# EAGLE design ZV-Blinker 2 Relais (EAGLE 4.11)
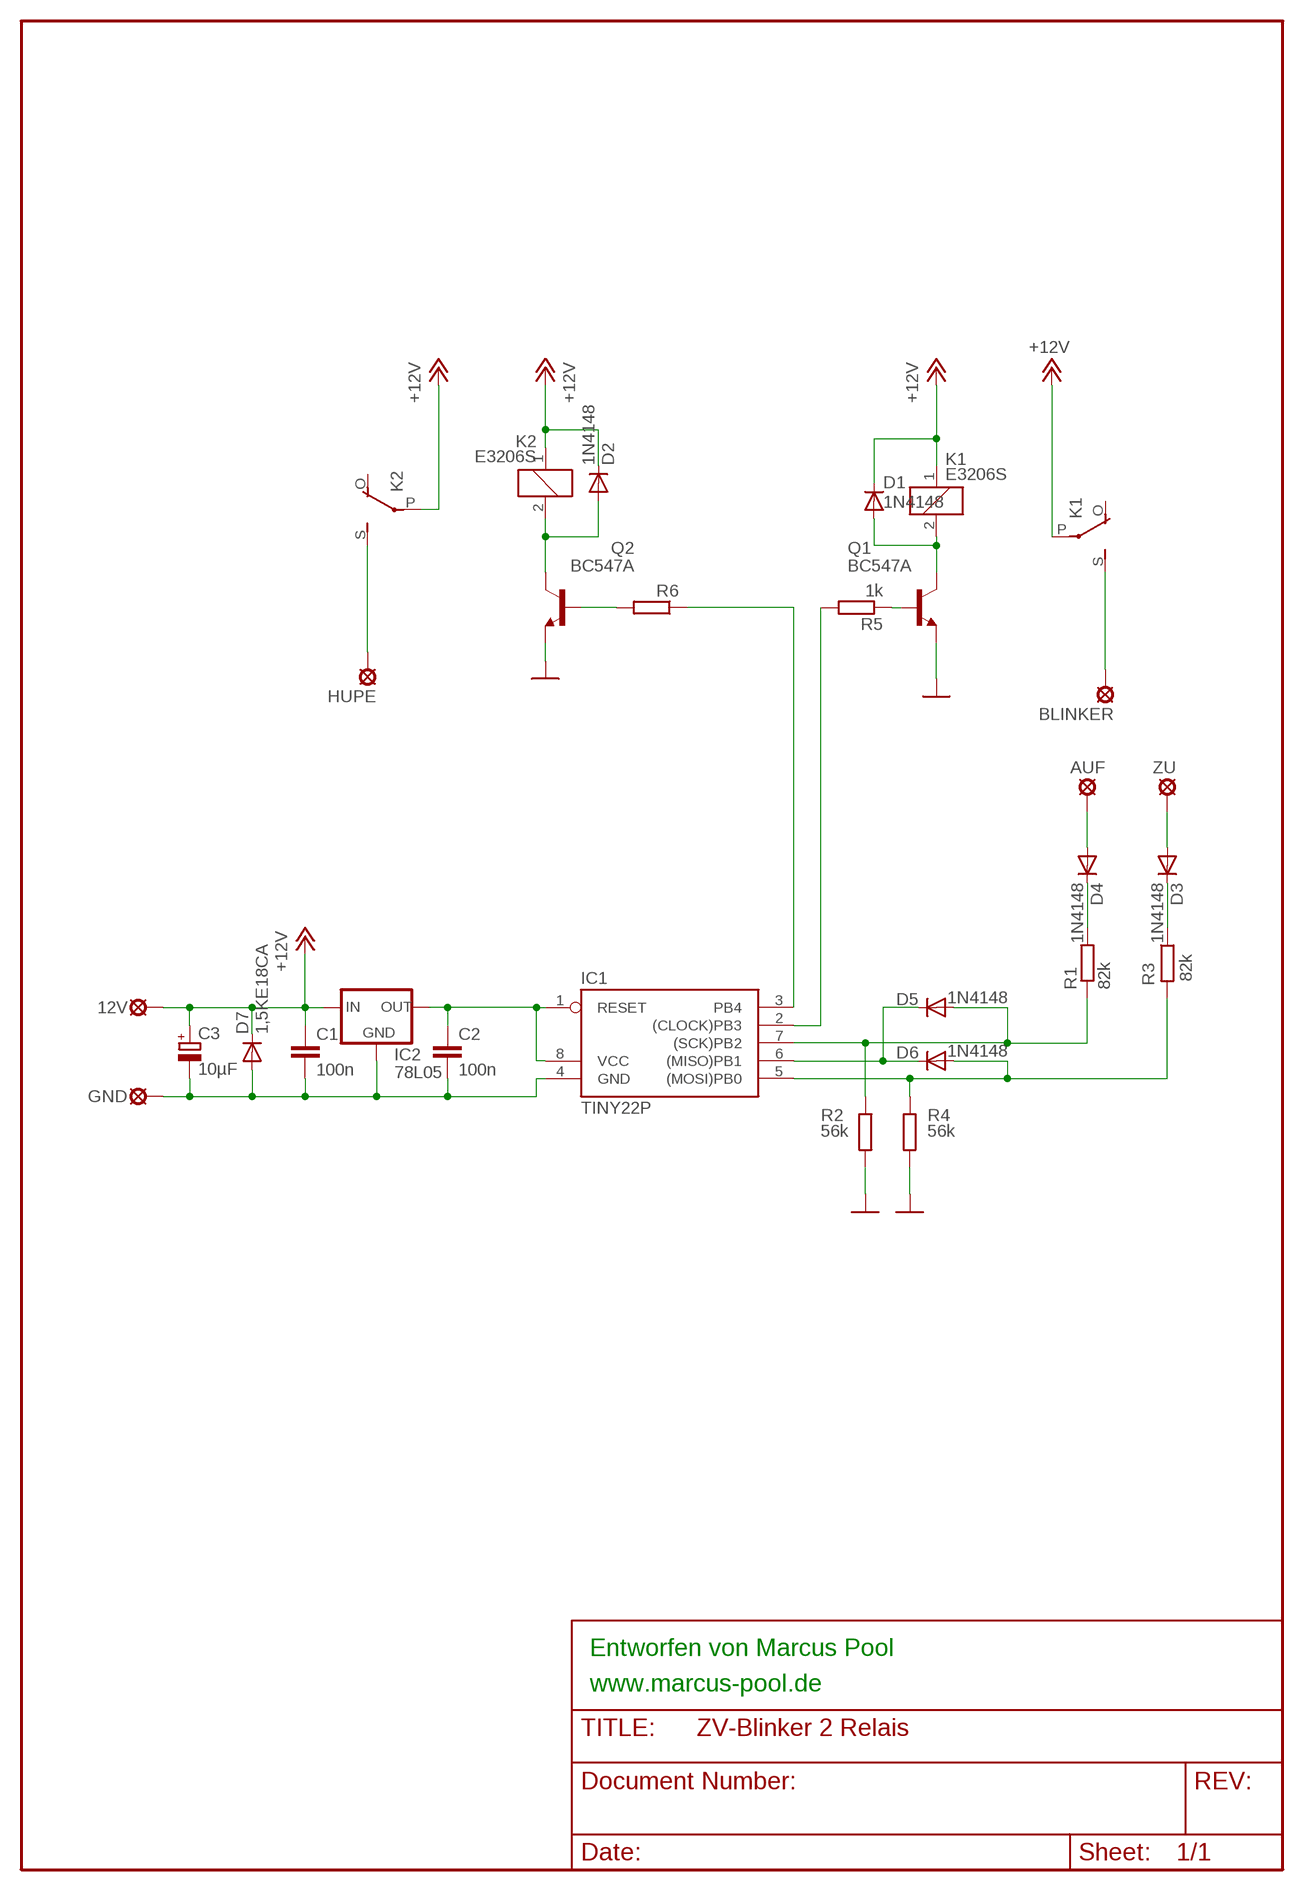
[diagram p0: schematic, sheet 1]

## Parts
12V  MCS08  [MCS08]
AUF  MCS08  [MCS08]
BLINKER  MCS08  [MCS08]
C1  100n  C-EU050-035X075  [C050-035X075]
C2  100n  C-EU050-035X075  [C050-035X075]
C3  10µF  CPOL-EUE2,5-6E  [E2,5-6E]
D1  1N4148  [DO35-10]
D2  1N4148  [DO35-10]
D3  1N4148  [DO35-10]
D4  1N4148  [DO35-10]
D5  1N4148  [DO35-10]
D6  1N4148  [DO35-10]
D7  1,5KE18CA  1N5060GP  [DO15-12]
GND  MCS08  [MCS08]
HUPE  MCS08  [MCS08]
IC1  TINY22P  [DIL08]
IC2  78L05  78LXX  [78LXX]
K1  E3206S  [E3206S]
K2  E3206S  [E3206S]
Q1  BC547A  [TO92]
Q2  BC547A  [TO92]
R1  82k  R-EU_0207/10  [0207/10]
R2  56k  R-EU_0207/10  [0207/10]
R3  82k  R-EU_0207/10  [0207/10]
R4  56k  R-EU_0207/10  [0207/10]
R5  1k  R-EU_0207/10  [0207/10]
R6  R-EU_0207/10  [0207/10]
ZU  MCS08  [MCS08]

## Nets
5V: C2.2 IC1.1(RESET) IC1.8(VCC) IC2.OUT
+12V: 12V.MP C1.2 C3.+ D1.C D2.C D7.C IC2.IN K1.1 K1.P(2:P) K2.1 K2.P(2:P)
GND: C1.1 C2.1 C3.- D7.A GND.MP IC1.4(GND) IC2.GND Q1.1(E) Q2.1(E) R2.2 R4.2 ; supply symbol labelled 
N$1: D5.A IC1.7((SCK)PB2) R1.1 R2.1
N$2: D5.C D6.C IC1.6((MISO)PB1)
N$3: BLINKER.MP K1.S(2:S)
N$4: D6.A IC1.5((MOSI)PB0) R3.2 R4.1
N$5: D3.A ZU.MP
N$6: Q1.2(B) R5.1
N$7: D1.A K1.2 Q1.3(C)
N$8: D3.C R3.1
N$9: AUF.MP D4.A
N$10: IC1.2((CLOCK)PB3) R5.2
N$11: D4.C R1.2
N$12: IC1.3(PB4) R6.1
N$13: Q2.2(B) R6.2
N$14: D2.A K2.2 Q2.3(C)
N$15: HUPE.MP K2.S(2:S)
Unconnected: K1.O(2:O) K2.O(2:O)

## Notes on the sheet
- Entworfen von Marcus Pool
- www.marcus-pool.de

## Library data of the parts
12V AUF BLINKER GND HUPE ZU = solpad:MCS08: SOLDER PAD
C1 C2 = rcl:C-EU: CAPACITOR, European symbol
C3 = rcl:CPOL-EU: POLARIZED CAPACITOR, European symbol
D1-D6 = diode:1N4148: DIODE
D7 = diode:1N5060GP: DIODE
IC1 = atmel:TINY22: MICROCONTROLLER 1K ROM 128 bytes RAM 128 bytes EEPROM
IC2 = v-reg:78LXX: VOLTAGE REGULATOR
K1 K2 = relay:E3206S: RELAY 1 x switch, Eichhoff/distributor Schukat
Q1 Q2 = transistor-npn:BC547*: NPN Transistor
R1-R6 = rcl:R-EU_: RESISTOR, European symbol

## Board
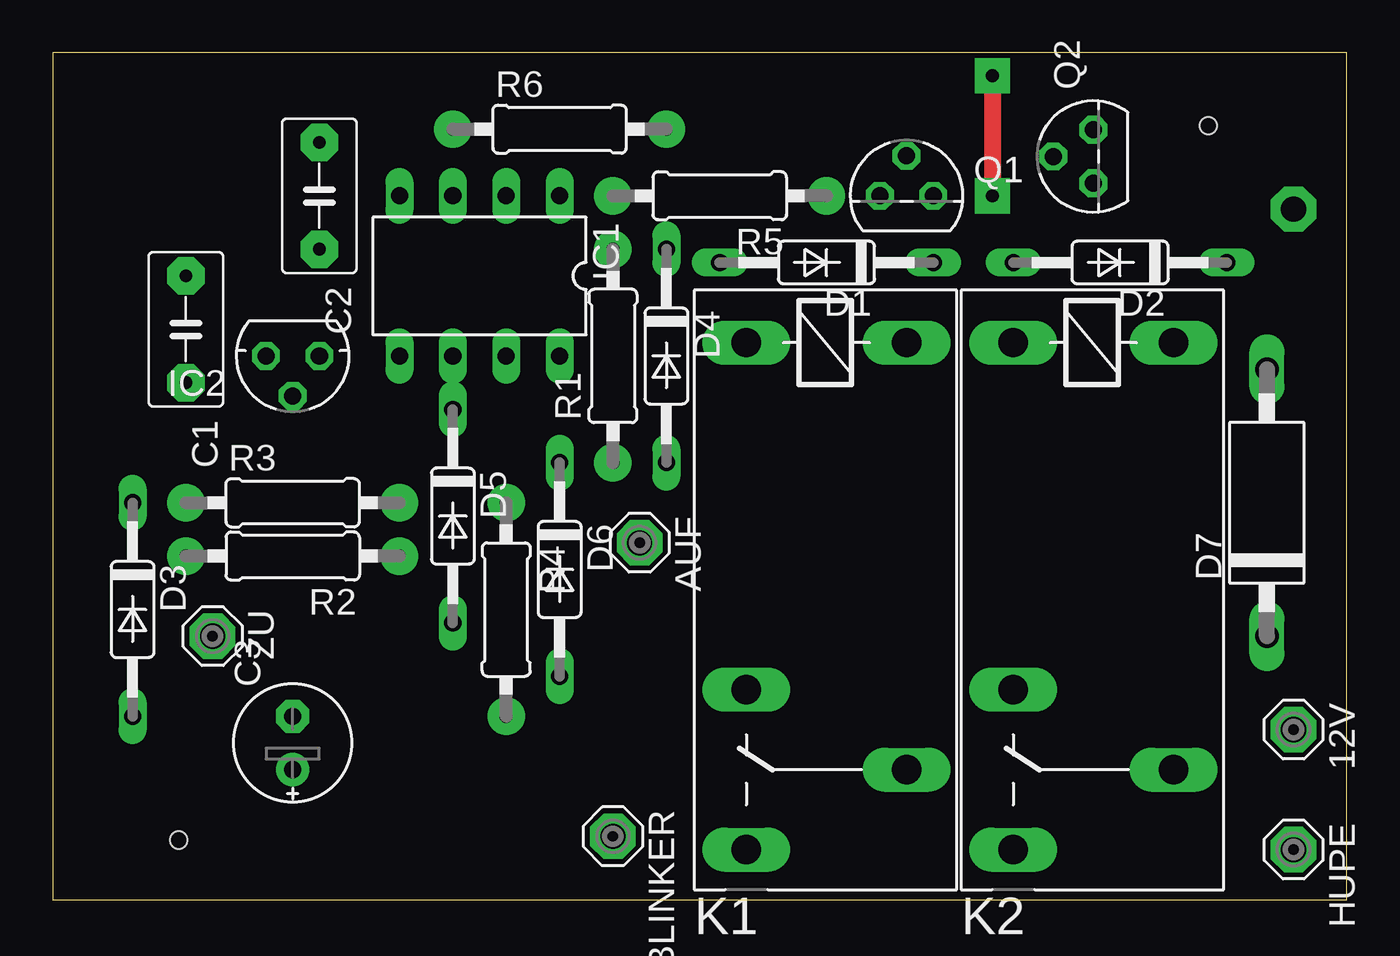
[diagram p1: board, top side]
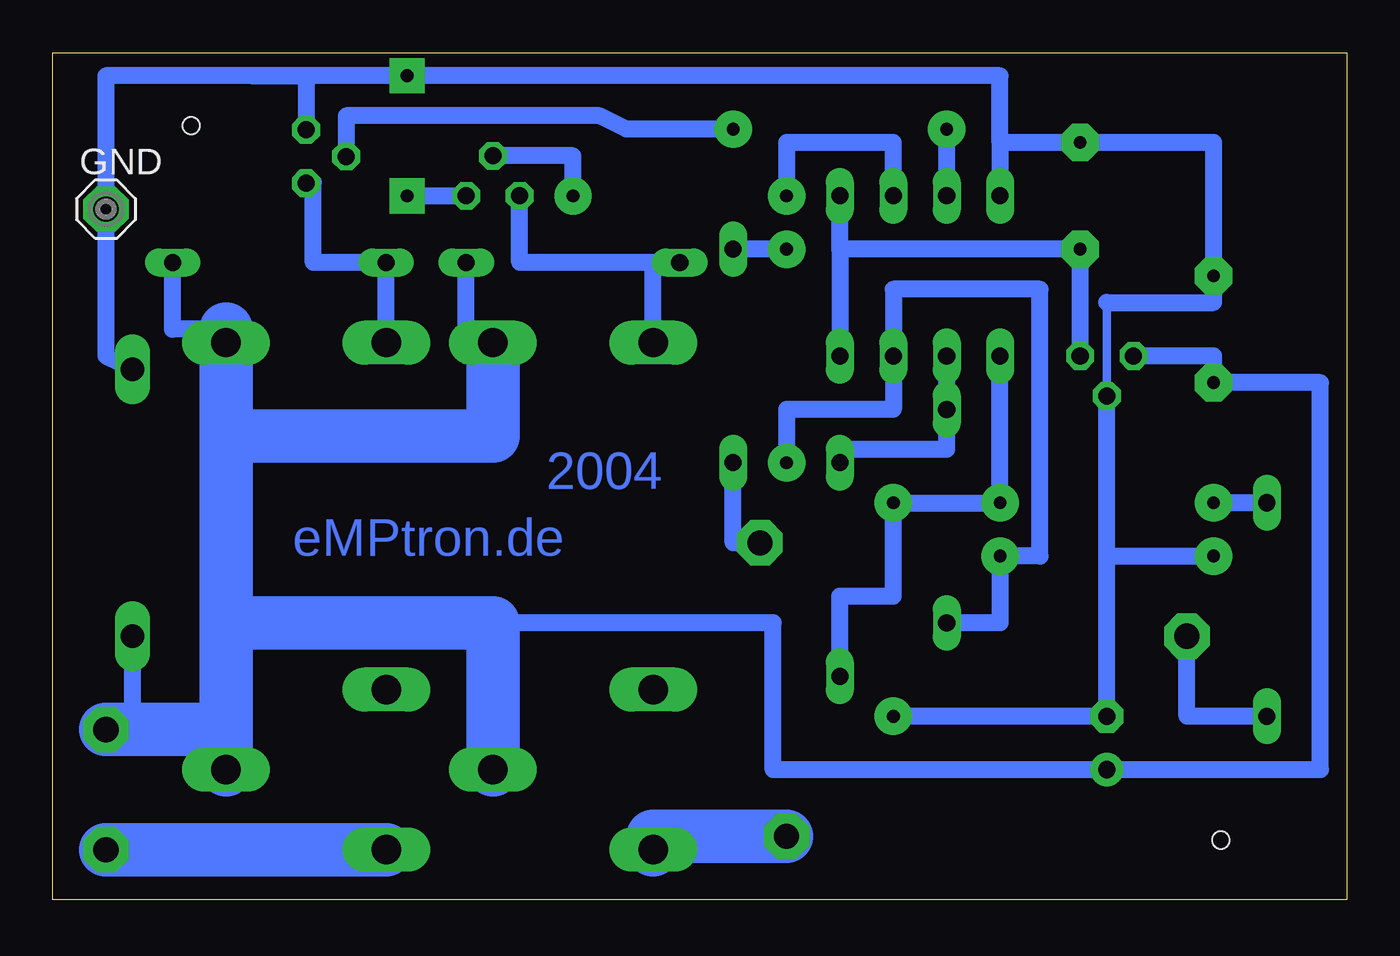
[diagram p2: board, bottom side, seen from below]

Size 61.59 x 40.31 mm. Coordinates in mm from the lower left corner, seen from the top.
Outline: 0,40.31 0,0 61.59,0 61.59,40.31 0,40.31
Copper layers (1*16): Top 0.035mm / dielectric 1.5mm / Bottom 0.035mm
Design rules "default": minimum track width 10mil, minimum drill 24mil, track to track 8mil, track to pad 8mil, pad to pad 8mil, via to via 8mil, smd to smd 8mil, copper to edge 40mil, drill to drill 8mil, minimum pad ring 10mil, minimum via ring 8mil, stop-mask expansion 4mil, vias tented up to drill 0mil, thermal gap 10mil
Holes 0.81 mm at 6,2.83 54.99,36.84

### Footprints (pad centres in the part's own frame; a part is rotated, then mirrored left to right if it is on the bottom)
MCS08 = drill 1.194 pad 2.159 octagon: MP 0,0
C050-035X075 = drill 0.61 pad 1.778 octagon: 1 -2.54,0; 2 2.54,0
E2,5-6E = drill 0.813 pad 1.575 round: + -1.27,0 | drill 0.813 pad 1.575 octagon: - 1.27,0
DO35-10 = drill 0.813 long: A 5.08,0; C -5.08,0
DO15-12 = drill 1.118 long: A 6.35,0; C -6.35,0
DIL08 = drill 0.813 long: 1 -3.81,-3.81; 2 -1.27,-3.81; 3 1.27,-3.81; 4 3.81,-3.81; 5 3.81,3.81; 6 1.27,3.81; 7 -1.27,3.81; 8 -3.81,3.81
78LXX = drill 0.813 octagon: GND 0,1.905; IN 1.27,0; OUT -1.27,0
E3206S = drill 1.397 long: 1 -3.175,3.81; 2 -3.175,-3.81; O 13.335,-3.81; P 17.145,3.81; S 20.955,-3.81
TO92 = drill 0.813 octagon: 1 1.27,0; 2 0,1.905; 3 -1.27,0
0207/10 = drill 0.61 pad 1.778 round: 1 -5.08,0; 2 5.08,0

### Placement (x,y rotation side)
12V  59.05,8.09 270 top
AUF  27.94,16.98 270 top
BLINKER  26.67,3.01 270 top
C1  6.34,27.14 270 top
C2  12.69,33.49 270 top
C3  11.42,7.46 90 top
D1  36.82,30.32 180 top
D2  50.79,30.32 180 top
D3  3.81,13.81 270 top
D4  29.21,25.87 270 top
D5  19.05,18.25 270 top
D6  24.12,15.71 270 top
D7  57.78,18.89 90 top
GND  59.05,32.86 0 bottom
HUPE  59.05,2.38 270 top
IC1  20.32,29.68 180 top
IC2  11.42,25.87 180 top
K1  36.82,23.33 270 top
K2  49.52,23.33 270 top
Q1  40.63,33.49 0 top
Q2  49.52,35.36 90 top
R1  26.67,25.87 90 top
R2  11.42,16.35 180 top
R3  11.42,18.89 0 top
R4  21.59,13.81 270 top
R5  31.75,33.49 180 top
R6  24.12,36.66 0 top
ZU  7.62,12.54 270 top

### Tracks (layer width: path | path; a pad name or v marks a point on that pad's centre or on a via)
5V
  Bottom 0.813: 24.12,30.95 IC1.1 | 24.12,30.95 IC1.8 | 24.12,30.95 C2.2 IC2.OUT
+12V
  Bottom 0.813: D2.C 55.88,27.14 53.34,27.14 K2.1 | K1.1 40.63,25.87 41.9,25.87 D1.C | IC2.IN 6.34,25.87 C1.2 1.27,24.6 1.27,6.18 C3.+ 27.3,6.18 27.3,13.17 40.63,13.17 | 12V.MP 57.78,8.09 D7.C
  Bottom 2.54: 53.34,22.06 53.34,27.14 | 53.34,13.17 53.34,22.06 | 53.34,13.17 K2.P | K1.P 40.63,13.17 53.34,13.17 | 40.63,25.87 40.63,22.06 53.34,22.06 | 53.34,13.17 53.34,8.09 12V.MP
GND  (via drill 0.61 pad 1.68)
  Top 0.813: v44.71,39.2 v44.71,33.49
  Bottom 0.406: IC2.GND 11.42,28.41
  Bottom 0.813: 11.42,16.35 R2.2 | R4.2 C3.- 11.42,16.35 | 16.51,36.03 IC1.4 | 16.51,36.03 C2.1 6.34,36.03 C1.1 6.34,28.41 11.42,28.41 | 16.51,36.03 16.51,39.2 v44.71,39.2 52.06,39.2 | 11.42,16.35 IC2.GND | v44.71,33.49 Q1.1 | 52.06,39.2 49.52,39.2 Q2.1 | 52.06,39.2 59.05,39.2 GND.MP 59.05,25.87 D7.A
N$1
  Bottom 0.813: D5.A 16.51,13.17 R2.1 14.6,16.35 14.6,29.05 21.59,29.05 IC1.7 21.59,23.33 26.67,23.33 R1.1
N$2
  Bottom 0.813: D6.C 24.12,21.43 19.05,21.43 D5.C IC1.6
N$3
  Bottom 2.54: K1.S 33.02,3.01 BLINKER.MP
N$4
  Bottom 0.813: D6.A 24.12,14.44 21.59,14.44 R4.1 R3.2 IC1.5
N$5
  Bottom 0.813: D3.A 7.62,8.73 ZU.MP
N$6
  Bottom 0.813: R5.1 36.82,35.4 Q1.2
N$7
  Bottom 0.813: 33.02,30.32 39.36,30.32 Q1.3 | K1.2 33.02,30.32 | 33.02,30.32 D1.A
N$8
  Bottom 0.813: D3.C R3.1
N$9
  Bottom 0.813: AUF.MP 29.21,16.98 D4.A
N$10
  Bottom 0.813: IC1.2 21.59,36.03 26.67,36.03 R5.2
N$11
  Bottom 0.813: R1.2 D4.C
N$12
  Bottom 0.813: IC1.3 R6.1
N$13
  Bottom 0.813: Q2.2 47.62,37.3 35.55,37.3 34.28,36.66 R6.2
N$14
  Bottom 0.813: K2.2 D2.A 49.18,30.32 49.18,34.12 Q2.3
N$15
  Bottom 0.813: K2.S 46.98,3.01
  Bottom 2.54: K2.S HUPE.MP

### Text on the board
Bottom: 2004 | eMPtron.de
